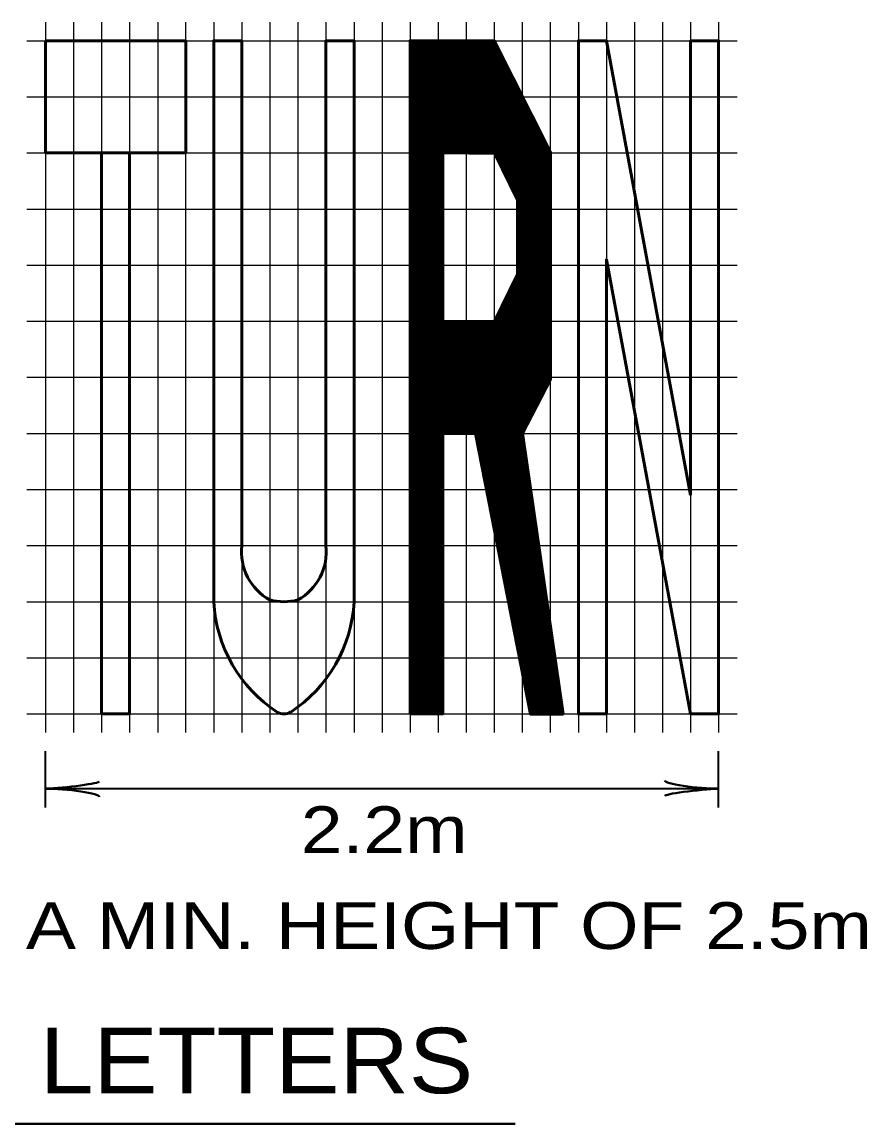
# Model space of a CAD drawing. Extents: x -96 to 617, y -65 to 388.
# Drawn here: x 37.5 to 82.7, y 201.3 to 260.3 of the extents above; entities that cross this region are included whole.
import ezdxf

# ---------------------------------------------------------------- set-up
doc = ezdxf.new("R2010")
doc.units = 0
doc.layers.add('1', color=7, linetype='Continuous', lineweight=53)

msp = doc.modelspace()

# ---------------------------------------------------------------- linework, layer by layer
at = {"layer": '1', "lineweight": 25}
for p, q in [((38.79, 260.267), (38.79, 222.267)), ((40.29, 260.267), (40.29, 222.267)), ((41.79, 260.267), (41.79, 222.267)), ((43.29, 260.267), (43.29, 222.267)), ((44.79, 260.267), (44.79, 222.267)), ((46.29, 222.267), (46.29, 260.267)), ((47.79, 260.267), (47.79, 222.267)), ((49.29, 260.267), (49.29, 222.267)), ((50.79, 260.267), (50.79, 222.267)), ((52.29, 260.267), (52.29, 222.267)), ((53.79, 260.267), (53.79, 222.267)), ((55.29, 260.267), (55.29, 222.267)), ((56.79, 260.267), (56.79, 222.267)), ((58.29, 260.267), (58.29, 222.267)), ((59.79, 260.267), (59.79, 222.267)), ((61.29, 260.267), (61.29, 222.267)), ((62.79, 260.267), (62.79, 222.267)), ((64.29, 260.267), (64.29, 222.267)), ((65.79, 260.267), (65.79, 222.267)), ((67.29, 260.267), (67.29, 222.267)), ((68.79, 260.267), (68.79, 222.267)), ((70.29, 260.267), (70.29, 222.267)), ((71.79, 260.267), (71.79, 222.267)), ((73.29, 260.267), (73.29, 222.267)), ((74.79, 260.267), (74.79, 222.267)), ((37.79, 259.267), (75.79, 259.267)), ((37.79, 256.267), (75.79, 256.267)), ((37.79, 253.267), (75.79, 253.267)), ((37.79, 250.267), (75.79, 250.267)), ((37.79, 247.267), (75.79, 247.267)), ((37.79, 244.267), (75.79, 244.267)), ((37.79, 241.267), (75.79, 241.267)), ((37.79, 238.267), (75.79, 238.267)), ((37.79, 235.267), (75.79, 235.267)), ((37.79, 232.267), (75.79, 232.267)), ((37.79, 229.267), (48.29, 229.267)), ((56.29, 229.267), (75.79, 229.267)), ((37.79, 226.267), (75.79, 226.267))]:
    msp.add_line(p, q, dxfattribs=at)
at = {"layer": '1'}
for p, q in [((58.29, 259.122), (58.435, 259.267)), ((58.29, 258.945), (58.612, 259.267)), ((58.29, 258.769), (58.789, 259.267)), ((58.29, 258.592), (58.966, 259.267)), ((58.29, 258.415), (59.143, 259.267)), ((58.29, 258.238), (59.319, 259.267)), ((58.29, 258.061), (59.496, 259.267)), ((58.29, 257.885), (59.673, 259.267)), ((58.29, 257.708), (59.85, 259.267)), ((58.29, 257.531), (60.026, 259.267)), ((58.29, 257.354), (60.203, 259.267)), ((58.29, 257.178), (60.38, 259.267)), ((58.29, 257.001), (60.557, 259.267)), ((58.29, 256.824), (60.734, 259.267)), ((58.29, 256.647), (60.91, 259.267)), ((58.29, 256.47), (61.087, 259.267)), ((58.29, 256.294), (61.264, 259.267)), ((58.29, 256.117), (61.441, 259.267)), ((58.29, 255.94), (61.617, 259.267)), ((58.29, 255.763), (61.794, 259.267)), ((58.29, 255.587), (61.971, 259.267)), ((58.29, 255.41), (62.148, 259.267)), ((58.29, 255.233), (62.325, 259.267)), ((58.29, 255.056), (62.501, 259.267)), ((58.29, 254.879), (62.678, 259.267)), ((58.29, 254.703), (62.812, 259.224)), ((58.29, 254.526), (62.871, 259.107)), ((58.29, 254.349), (62.931, 258.989)), ((58.29, 254.172), (62.99, 258.872)), ((58.29, 253.996), (63.049, 258.754)), ((58.29, 253.819), (63.108, 258.637)), ((58.29, 253.642), (63.168, 258.519)), ((58.29, 253.465), (63.227, 258.402)), ((58.29, 253.288), (63.286, 258.284)), ((58.29, 253.112), (63.345, 258.167)), ((58.29, 252.935), (63.405, 258.049)), ((58.29, 252.758), (63.464, 257.932)), ((58.29, 252.581), (63.523, 257.814)), ((58.29, 252.405), (63.582, 257.697)), ((58.29, 252.228), (63.642, 257.579)), ((58.29, 252.051), (63.701, 257.462)), ((58.29, 251.874), (63.76, 257.344)), ((58.29, 251.697), (63.819, 257.227)), ((58.29, 251.521), (63.879, 257.109)), ((60.21, 253.264), (63.938, 256.991)), ((60.386, 253.262), (63.997, 256.874)), ((60.561, 253.261), (64.057, 256.757)), ((60.736, 253.26), (64.116, 256.639)), ((60.912, 253.258), (64.175, 256.522)), ((61.087, 253.257), (64.234, 256.404)), ((61.262, 253.255), (64.294, 256.286)), ((61.438, 253.254), (64.353, 256.169)), ((61.613, 253.252), (64.412, 256.051)), ((61.789, 253.251), (64.471, 255.934)), ((61.964, 253.25), (64.531, 255.816)), ((62.139, 253.248), (64.59, 255.699)), ((62.315, 253.247), (64.649, 255.581)), ((62.49, 253.245), (64.708, 255.464)), ((62.665, 253.244), (64.768, 255.346)), ((62.826, 253.228), (64.827, 255.229)), ((62.884, 253.11), (64.886, 255.111)), ((62.943, 252.991), (64.945, 254.994)), ((63.001, 252.873), (65.005, 254.876)), ((63.06, 252.754), (65.064, 254.759)), ((63.118, 252.636), (65.123, 254.641)), ((63.177, 252.518), (65.183, 254.524)), ((63.235, 252.399), (65.242, 254.406)), ((63.293, 252.281), (65.301, 254.289)), ((63.352, 252.163), (65.36, 254.171)), ((63.41, 252.044), (65.42, 254.054)), ((63.469, 251.926), (65.479, 253.936)), ((63.527, 251.808), (65.538, 253.819)), ((63.585, 251.689), (65.597, 253.701)), ((63.644, 251.571), (65.657, 253.584)), ((63.702, 251.452), (65.716, 253.466)), ((58.29, 251.344), (60.04, 253.094)), ((58.29, 251.167), (60.04, 252.917)), ((63.761, 251.334), (65.775, 253.349)), ((63.819, 251.216), (65.805, 253.201)), ((63.877, 251.097), (65.805, 253.025)), ((63.936, 250.979), (65.805, 252.848)), ((58.29, 250.99), (60.04, 252.74)), ((58.29, 250.814), (60.04, 252.564)), ((58.29, 250.637), (60.04, 252.387)), ((63.994, 250.861), (65.805, 252.671)), ((64.04, 250.73), (65.805, 252.494)), ((64.04, 250.553), (65.805, 252.317)), ((58.29, 250.46), (60.04, 252.21)), ((58.29, 250.283), (60.04, 252.033)), ((58.29, 250.106), (60.04, 251.856)), ((58.29, 249.93), (60.04, 251.68)), ((64.04, 250.376), (65.805, 252.141)), ((64.04, 250.2), (65.805, 251.964)), ((64.04, 250.023), (65.805, 251.787)), ((58.29, 249.753), (60.04, 251.503)), ((58.29, 249.576), (60.04, 251.326)), ((58.29, 249.399), (60.04, 251.149)), ((64.04, 249.846), (65.805, 251.61)), ((64.04, 249.669), (65.805, 251.434)), ((64.04, 249.492), (65.805, 251.257)), ((64.04, 249.316), (65.805, 251.08)), ((58.29, 249.223), (60.04, 250.973)), ((58.29, 249.046), (60.04, 250.796)), ((58.29, 248.869), (60.04, 250.619)), ((64.04, 249.139), (65.805, 250.903)), ((64.04, 248.962), (65.805, 250.726)), ((64.04, 248.785), (65.805, 250.55)), ((58.29, 248.692), (60.04, 250.442)), ((58.29, 248.516), (60.04, 250.266)), ((58.29, 248.339), (60.04, 250.089)), ((58.29, 248.162), (60.04, 249.912)), ((64.04, 248.609), (65.805, 250.373)), ((64.04, 248.432), (65.805, 250.196)), ((64.04, 248.255), (65.805, 250.019)), ((58.29, 247.985), (60.04, 249.735)), ((58.29, 247.808), (60.04, 249.558)), ((58.29, 247.632), (60.04, 249.382)), ((64.04, 248.078), (65.805, 249.843)), ((64.04, 247.901), (65.805, 249.666)), ((64.04, 247.725), (65.805, 249.489)), ((64.04, 247.548), (65.805, 249.312)), ((58.29, 247.455), (60.04, 249.205)), ((58.29, 247.278), (60.04, 249.028)), ((58.29, 247.101), (60.04, 248.851)), ((64.04, 247.371), (65.805, 249.135)), ((64.04, 247.194), (65.805, 248.959)), ((64.04, 247.018), (65.805, 248.782)), ((58.29, 246.924), (60.04, 248.674)), ((58.29, 246.748), (60.04, 248.498)), ((58.29, 246.571), (60.04, 248.321)), ((58.29, 246.394), (60.04, 248.144)), ((63.769, 246.216), (65.805, 248.252)), ((63.941, 246.564), (65.805, 248.428)), ((64.04, 246.841), (65.805, 248.605)), ((58.29, 246.217), (60.04, 247.967)), ((58.29, 246.041), (60.04, 247.791)), ((58.29, 245.864), (60.04, 247.614)), ((63.084, 244.824), (65.805, 247.544)), ((63.255, 245.172), (65.805, 247.721)), ((63.427, 245.52), (65.805, 247.898)), ((63.598, 245.868), (65.805, 248.075)), ((58.29, 245.687), (60.04, 247.437)), ((58.29, 245.51), (60.04, 247.26)), ((58.29, 239.677), (65.805, 247.191)), ((58.29, 245.333), (60.04, 247.083)), ((58.29, 239.5), (65.805, 247.014)), ((62.913, 244.476), (65.805, 247.368)), ((58.29, 245.157), (60.04, 246.907)), ((58.29, 239.323), (65.805, 246.837)), ((58.29, 244.98), (60.04, 246.73)), ((58.29, 239.146), (65.805, 246.661)), ((58.29, 244.803), (60.04, 246.553)), ((58.29, 238.97), (65.805, 246.484)), ((58.29, 244.626), (60.04, 246.376)), ((58.29, 238.793), (65.805, 246.307)), ((58.29, 244.45), (60.04, 246.2)), ((58.29, 238.616), (65.805, 246.13)), ((58.29, 244.273), (60.04, 246.023)), ((58.29, 238.439), (65.805, 245.954)), ((58.29, 244.096), (60.04, 245.846)), ((58.29, 238.262), (65.805, 245.777)), ((58.29, 243.919), (60.04, 245.669)), ((58.29, 238.086), (65.805, 245.6)), ((58.29, 243.742), (60.04, 245.492)), ((58.29, 237.909), (65.805, 245.423)), ((58.29, 243.566), (60.04, 245.316)), ((58.29, 237.732), (65.805, 245.246)), ((58.29, 243.389), (60.04, 245.139)), ((58.29, 237.555), (65.805, 245.07)), ((58.29, 243.212), (60.04, 244.962)), ((58.29, 237.379), (65.805, 244.893)), ((58.29, 243.035), (60.04, 244.785)), ((58.29, 237.202), (65.805, 244.716)), ((58.29, 242.859), (60.04, 244.609)), ((58.29, 237.025), (65.805, 244.539)), ((58.29, 242.682), (60.04, 244.432)), ((58.29, 236.848), (65.805, 244.363)), ((58.29, 242.505), (60.051, 244.266)), ((58.29, 242.328), (60.227, 244.264)), ((58.29, 242.151), (60.402, 244.263)), ((58.29, 241.975), (60.578, 244.262)), ((58.29, 241.798), (60.753, 244.261)), ((58.29, 241.621), (60.929, 244.26)), ((58.29, 241.444), (61.105, 244.259)), ((58.29, 241.268), (61.28, 244.258)), ((58.29, 241.091), (61.456, 244.256)), ((58.29, 240.914), (61.632, 244.255)), ((58.29, 240.737), (61.807, 244.254)), ((58.29, 240.56), (61.983, 244.253)), ((58.29, 240.384), (62.159, 244.252)), ((58.29, 240.207), (62.334, 244.251)), ((58.29, 240.03), (62.51, 244.25)), ((58.29, 239.853), (62.686, 244.249)), ((58.29, 236.671), (65.805, 244.186)), ((60.063, 238.267), (65.805, 244.009)), ((60.24, 238.267), (65.805, 243.832)), ((60.416, 238.267), (65.805, 243.655)), ((60.593, 238.267), (65.805, 243.479)), ((60.77, 238.267), (65.805, 243.302)), ((60.947, 238.267), (65.805, 243.125)), ((61.124, 238.267), (65.805, 242.948)), ((61.3, 238.267), (65.805, 242.772)), ((61.477, 238.267), (65.805, 242.595)), ((61.654, 238.267), (65.805, 242.418)), ((61.797, 238.233), (65.805, 242.241)), ((61.826, 238.086), (65.805, 242.064)), ((61.855, 237.938), (65.805, 241.888)), ((61.884, 237.79), (65.805, 241.711)), ((61.913, 237.642), (65.805, 241.534)), ((61.941, 237.494), (65.805, 241.357)), ((61.97, 237.346), (65.805, 241.181)), ((61.999, 237.198), (65.629, 240.828)), ((62.028, 237.05), (65.438, 240.46)), ((62.057, 236.903), (65.247, 240.093)), ((62.086, 236.755), (65.057, 239.725)), ((62.115, 236.607), (64.866, 239.358)), ((62.144, 236.459), (64.675, 238.99)), ((58.29, 236.495), (60.04, 238.245)), ((62.172, 236.311), (64.484, 238.623)), ((62.201, 236.163), (64.305, 238.266)), ((62.23, 236.015), (64.327, 238.112)), ((58.29, 236.318), (60.04, 238.068)), ((58.29, 236.141), (60.04, 237.891)), ((58.29, 235.964), (60.04, 237.714)), ((58.29, 235.788), (60.04, 237.538)), ((62.259, 235.867), (64.349, 237.958)), ((62.288, 235.719), (64.372, 237.803)), ((62.317, 235.571), (64.394, 237.649)), ((62.346, 235.424), (64.416, 237.494)), ((58.29, 235.611), (60.04, 237.361)), ((58.29, 235.434), (60.04, 237.184)), ((58.29, 235.257), (60.04, 237.007)), ((62.375, 235.276), (64.439, 237.34)), ((62.404, 235.128), (64.461, 237.185)), ((62.432, 234.98), (64.483, 237.031)), ((58.29, 235.081), (60.04, 236.831)), ((58.29, 234.904), (60.04, 236.654)), ((58.29, 234.727), (60.04, 236.477)), ((62.461, 234.832), (64.506, 236.876)), ((62.49, 234.684), (64.528, 236.722)), ((62.519, 234.536), (64.55, 236.567)), ((62.548, 234.388), (64.572, 236.413)), ((58.29, 234.55), (60.04, 236.3)), ((58.29, 234.373), (60.04, 236.123)), ((58.29, 234.197), (60.04, 235.947)), ((58.29, 234.02), (60.04, 235.77)), ((62.577, 234.24), (64.595, 236.258)), ((62.606, 234.093), (64.617, 236.104)), ((62.635, 233.945), (64.639, 235.949)), ((62.664, 233.797), (64.662, 235.795)), ((58.29, 233.843), (60.04, 235.593)), ((58.29, 233.666), (60.04, 235.416)), ((58.29, 233.489), (60.04, 235.239)), ((62.692, 233.649), (64.684, 235.641)), ((62.721, 233.501), (64.706, 235.486)), ((62.75, 233.353), (64.729, 235.332)), ((62.779, 233.205), (64.751, 235.177)), ((58.29, 233.313), (60.04, 235.063)), ((58.29, 233.136), (60.04, 234.886)), ((58.29, 232.959), (60.04, 234.709)), ((62.808, 233.057), (64.773, 235.023)), ((62.837, 232.909), (64.796, 234.868)), ((62.866, 232.762), (64.818, 234.714)), ((62.895, 232.614), (64.84, 234.559)), ((58.29, 232.782), (60.04, 234.532)), ((58.29, 232.606), (60.04, 234.356)), ((58.29, 232.429), (60.04, 234.179)), ((58.29, 232.252), (60.04, 234.002)), ((62.924, 232.466), (64.862, 234.405)), ((62.953, 232.318), (64.885, 234.25)), ((62.981, 232.17), (64.907, 234.096)), ((58.29, 232.075), (60.04, 233.825)), ((58.29, 231.898), (60.04, 233.648)), ((58.29, 231.722), (60.04, 233.472)), ((63.01, 232.022), (64.929, 233.941)), ((63.039, 231.874), (64.952, 233.787)), ((63.068, 231.726), (64.974, 233.632)), ((63.097, 231.578), (64.996, 233.478)), ((58.29, 231.545), (60.04, 233.295)), ((58.29, 231.368), (60.04, 233.118)), ((58.29, 231.191), (60.04, 232.941)), ((63.126, 231.431), (65.019, 233.323)), ((63.155, 231.283), (65.041, 233.169)), ((63.184, 231.135), (65.063, 233.014)), ((63.212, 230.987), (65.086, 232.86)), ((58.29, 231.015), (60.04, 232.765)), ((58.29, 230.838), (60.04, 232.588)), ((58.29, 230.661), (60.04, 232.411)), ((58.29, 230.484), (60.04, 232.234)), ((63.241, 230.839), (65.108, 232.706)), ((63.27, 230.691), (65.13, 232.551)), ((63.299, 230.543), (65.153, 232.397)), ((63.328, 230.395), (65.175, 232.242)), ((58.29, 230.308), (60.04, 232.058)), ((58.29, 230.131), (60.04, 231.881)), ((58.29, 229.954), (60.04, 231.704)), ((63.357, 230.247), (65.197, 232.088)), ((63.386, 230.1), (65.219, 231.933)), ((63.415, 229.952), (65.242, 231.779)), ((63.444, 229.804), (65.264, 231.624)), ((58.29, 229.777), (60.04, 231.527)), ((58.29, 229.6), (60.04, 231.35)), ((58.29, 229.424), (60.04, 231.174)), ((63.472, 229.656), (65.286, 231.47)), ((63.501, 229.508), (65.309, 231.315)), ((63.53, 229.36), (65.331, 231.161)), ((63.559, 229.212), (65.353, 231.006)), ((58.29, 229.247), (60.04, 230.997)), ((58.29, 229.07), (60.04, 230.82)), ((58.29, 228.893), (60.04, 230.643)), ((58.29, 228.716), (60.04, 230.466)), ((63.588, 229.064), (65.376, 230.852)), ((63.617, 228.916), (65.398, 230.697)), ((63.646, 228.769), (65.42, 230.543)), ((58.29, 228.54), (60.04, 230.29)), ((58.29, 228.363), (60.04, 230.113)), ((58.29, 228.186), (60.04, 229.936)), ((63.675, 228.621), (65.442, 230.388)), ((63.704, 228.473), (65.465, 230.234)), ((63.732, 228.325), (65.487, 230.079)), ((63.761, 228.177), (65.509, 229.925)), ((58.29, 228.009), (60.04, 229.759)), ((58.29, 227.833), (60.04, 229.583)), ((58.29, 227.656), (60.04, 229.406)), ((63.79, 228.029), (65.532, 229.771)), ((63.819, 227.881), (65.554, 229.616)), ((63.848, 227.733), (65.576, 229.462)), ((63.877, 227.585), (65.599, 229.307)), ((58.29, 227.479), (60.04, 229.229)), ((58.29, 227.302), (60.04, 229.052)), ((58.29, 227.125), (60.04, 228.875)), ((58.29, 226.949), (60.04, 228.699)), ((63.906, 227.438), (65.621, 229.153)), ((63.935, 227.29), (65.643, 228.998)), ((63.963, 227.142), (65.665, 228.844)), ((63.992, 226.994), (65.688, 228.689)), ((58.29, 226.772), (60.04, 228.522)), ((58.29, 226.595), (60.04, 228.345)), ((58.29, 226.418), (60.04, 228.168)), ((64.021, 226.846), (65.71, 228.535)), ((64.05, 226.698), (65.732, 228.38)), ((64.079, 226.55), (65.755, 228.226)), ((64.108, 226.402), (65.777, 228.071)), ((58.29, 226.242), (60.04, 227.992)), ((58.29, 226.065), (60.04, 227.815)), ((58.29, 225.888), (60.04, 227.638)), ((64.137, 226.254), (65.799, 227.917)), ((64.166, 226.107), (65.822, 227.762)), ((64.195, 225.959), (65.844, 227.608)), ((58.29, 225.711), (60.04, 227.461)), ((58.29, 225.534), (60.04, 227.284)), ((58.29, 225.358), (60.04, 227.108)), ((58.29, 225.181), (60.04, 226.931)), ((64.224, 225.811), (65.866, 227.453)), ((64.252, 225.663), (65.889, 227.299)), ((64.281, 225.515), (65.911, 227.145)), ((64.31, 225.367), (65.933, 226.99)), ((58.29, 225.004), (60.04, 226.754)), ((58.29, 224.827), (60.04, 226.577)), ((58.29, 224.651), (60.04, 226.401)), ((64.339, 225.219), (65.956, 226.836)), ((64.368, 225.071), (65.978, 226.681)), ((64.397, 224.923), (66, 226.527)), ((64.426, 224.776), (66.022, 226.372)), ((58.29, 224.474), (60.04, 226.224)), ((58.29, 224.297), (60.04, 226.047)), ((58.29, 224.12), (60.04, 225.87)), ((64.455, 224.628), (66.045, 226.218)), ((64.483, 224.48), (66.067, 226.063)), ((64.512, 224.332), (66.089, 225.909)), ((64.541, 224.184), (66.112, 225.754)), ((58.29, 223.944), (60.04, 225.694)), ((58.29, 223.767), (60.04, 225.517)), ((58.29, 223.59), (60.04, 225.34)), ((58.29, 223.413), (60.04, 225.163)), ((64.57, 224.036), (66.134, 225.6)), ((64.599, 223.888), (66.156, 225.445)), ((64.628, 223.74), (66.178, 225.291)), ((64.657, 223.592), (66.201, 225.136)), ((58.321, 223.267), (60.04, 224.986)), ((58.498, 223.267), (60.04, 224.81)), ((58.675, 223.267), (60.04, 224.633)), ((64.686, 223.445), (66.223, 224.982)), ((64.715, 223.297), (66.245, 224.827)), ((64.854, 223.26), (66.268, 224.673)), ((58.852, 223.267), (60.04, 224.456)), ((59.028, 223.267), (60.04, 224.279)), ((59.205, 223.267), (60.04, 224.102)), ((65.031, 223.26), (66.29, 224.519)), ((65.208, 223.26), (66.312, 224.364)), ((65.385, 223.26), (66.335, 224.21)), ((65.561, 223.26), (66.357, 224.055)), ((59.382, 223.267), (60.04, 223.926)), ((59.559, 223.267), (60.04, 223.749)), ((59.735, 223.267), (60.04, 223.572)), ((59.912, 223.267), (60.04, 223.395)), ((65.738, 223.26), (66.379, 223.901)), ((65.915, 223.26), (66.402, 223.746)), ((66.092, 223.26), (66.424, 223.592)), ((66.269, 223.26), (66.446, 223.437)), ((66.445, 223.26), (66.468, 223.283))]:
    msp.add_line(p, q, dxfattribs=at)
at = {"layer": '1', "lineweight": 35}
for p, q in [((38.79, 218.267), (38.79, 221.267)), ((74.79, 218.267), (74.79, 221.267)), ((74.79, 219.267), (38.79, 219.267))]:
    msp.add_line(p, q, dxfattribs=at)
at = {"layer": '1', "lineweight": 40}
msp.add_line((3.989, 201.338), (63.905, 201.338), dxfattribs=at)
at = {"layer": '1'}
for points in [[(38.79, 259.267), (46.29, 259.267), (46.29, 253.267), (38.79, 253.267)], [(58.29, 223.267), (58.29, 259.267), (62.79, 259.267), (65.805, 253.29), (65.805, 241.167), (64.304, 238.275), (66.472, 223.26), (64.722, 223.26), (61.79, 238.267), (60.04, 238.267), (60.04, 223.267)], [(73.29, 234.967), (68.79, 259.267), (67.29, 259.267), (67.29, 223.267), (68.79, 223.267), (68.79, 247.567), (73.29, 223.267), (74.79, 223.267), (74.79, 259.267), (73.29, 259.267)], [(43.29, 253.267), (43.29, 223.267), (41.79, 223.267), (41.79, 253.267)], [(60.04, 244.266), (60.04, 253.265), (62.819, 253.243), (64.04, 250.767), (64.04, 246.767), (62.801, 244.248)]]:
    msp.add_lwpolyline(points, close=True, dxfattribs=at)
for points in [[(47.79, 229.267), (47.79, 259.267), (49.29, 259.267), (49.29, 232.267)], [(53.79, 232.267), (53.79, 259.267), (55.29, 259.267), (55.29, 229.267)]]:
    msp.add_lwpolyline(points, dxfattribs=at)
at = {"layer": '1', "lineweight": 25}
for points in [[(48.29, 229.267), (50.79, 229.267), (52.29, 229.267), (56.29, 229.267)], [(37.79, 223.267), (50.79, 223.267), (52.29, 223.267), (75.79, 223.267)]]:
    msp.add_lwpolyline(points, dxfattribs=at)
at = {"layer": '1'}
for centre, radius, start, end in [((52.211, 231.937), 2.939, 173.55629, 241.09244), ((50.869, 231.937), 2.939, 298.90756, 6.44371), ((55.299, 229.652), 7.519, 182.93171, 236.76354), ((51.54, 232.221), 2.954, 255.29363, 284.70637), ((47.782, 229.652), 7.519, 303.23646, 357.06829), ((51.54, 223.999), 0.732, 240.36844, 299.63156)]:
    msp.add_arc(centre, radius, start, end, dxfattribs=at)
at = {"layer": '1', "lineweight": 40}
for centre, major_axis, ratio, start_param, end_param in [((39.911, 219.479), (-1.756, -0.176), 0.07063, 0.865075, 3.142471), ((39.882, 218.991), (-1.786, 0.156), 0.122415, 3.141593, 5.386832), ((73.699, 219.543), (1.786, -0.156), 0.122415, 3.141593, 5.386832), ((73.699, 219.543), (1.786, -0.156), 0.122415, 3.141593, 5.386832), ((73.67, 219.056), (1.756, 0.176), 0.07063, 0.865075, 3.142471), ((73.67, 219.056), (1.756, 0.176), 0.07063, 0.865075, 3.142471)]:
    msp.add_ellipse(centre, major_axis=major_axis, ratio=ratio, start_param=start_param, end_param=end_param, dxfattribs=at)

# ---------------------------------------------------------------- texts
at = {"layer": '1'}
for s, height, width, p in [('2.2m', 2.5, 1.2, (52.446, 215.825)), ('ALL LETTERS SHALL HAVE A MIN. HEIGHT OF 2.5m', 2.5, 1.2, (-15.545, 210.698)), ('ELONGATED LETTERS', 3.5, 1.1, (5.302, 202.981))]:
    msp.add_text(s, height=height, dxfattribs=dict(at, width=width)).set_placement(p)

doc.saveas('drawing.dxf')
